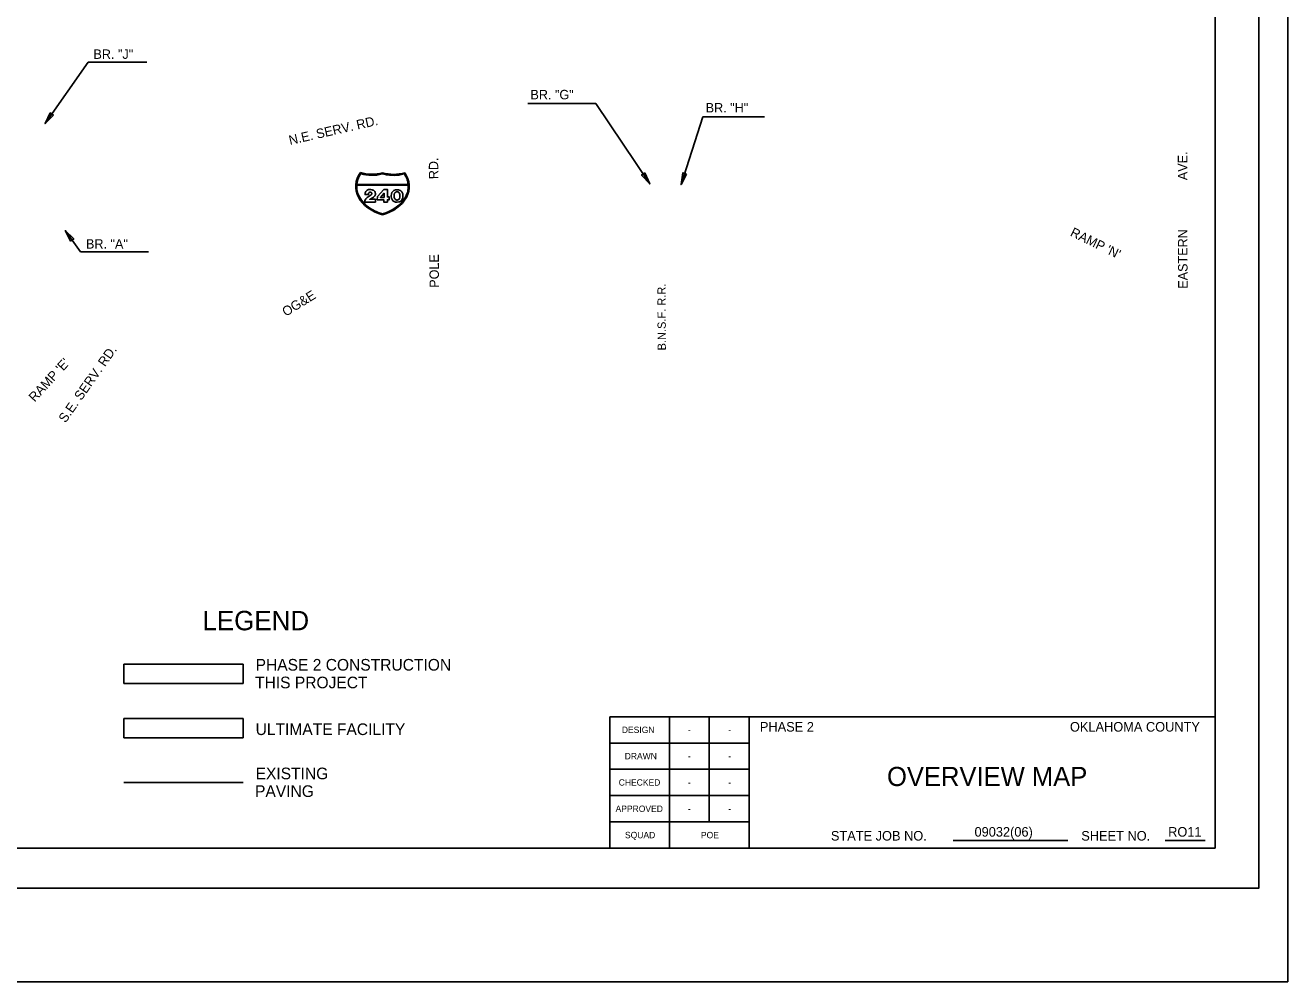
# Model space of a CAD drawing. Extents: x 2140911 to 2156666, y 139570 to 147689.
# Drawn here: x 2151304 to 2156666, y 139570 to 143629 of the extents above; entities that cross this region are included whole.
import ezdxf

# ---------------------------------------------------------------- set-up
doc = ezdxf.new("R2010")
doc.units = 0
for name, color, linetype in [('5', 7, 'Continuous'), ('7', 7, 'Continuous'), ('Default', 7, 'Continuous'), ('NEWCRK', 7, 'Continuous'), ('PR_Shading_Bridge_Phase_4', 7, 'Continuous'), ('PR_Shading_Pavement_Phase_3', 7, 'Continuous'), ('SHT_Plot_Shape_Full', 7, 'Continuous'), ('SHT_Plot_Shape_Half', 7, 'Continuous'), ('SHT_Sheet_Border', 7, 'Continuous'), ('SHT_Standard_Sheet_Lines', 7, 'Continuous'), ('SHT_Standard_Sheet_Txt', 7, 'Continuous'), ('ST-TEXT', 7, 'Continuous'), ('TOPO_Asphalt', 7, 'Continuous')]:
    doc.layers.add(name, color=color, linetype=linetype)

# ---------------------------------------------------------------- blocks, each defined once
blk = doc.blocks.new('ARROWHD')
at = {"layer": 'Default'}
blk.add_lwpolyline([(0.313, -0.054), (0.313, 0.052), (-0.005, -0.001)], close=True, dxfattribs=at)
blk = doc.blocks.new('i-240-shield')
at = {"layer": '7'}
blk.add_line((-18.14, 4.87), (18.76, 4.87), dxfattribs=at)
blk.add_line((-18.14, 4.87), (18.76, 4.87), dxfattribs=at)
for points in [[(-18.19, 4.17), (-18.21, 3.34), (-18.2, 2.74), (-18.15, 2.08), (-18.03, 1.02), (-17.84, 0.03), (-17.61, -0.87), (-17.3, -1.84), (-16.81, -3.04), (-16.3, -4.1), (-15.54, -5.4), (-14.75, -6.55), (-13.83, -7.71), (-12.99, -8.63), (-11.98, -9.62), (-11.44, -10.1), (-10.55, -10.85), (-9.63, -11.55), (-8.66, -12.22), (-7.48, -12.96), (-6.6, -13.47), (-5.36, -14.13), (-3.8, -14.86), (-2.74, -15.3), (-1.39, -15.81), (-0.45, -16.12), (0.31, -16.36), (1.08, -16.12), (2.01, -15.81), (3.36, -15.3), (4.42, -14.86), (5.98, -14.13), (7.23, -13.47), (8.11, -12.96), (9.29, -12.22), (10.26, -11.55), (11.17, -10.85), (12.07, -10.1), (12.61, -9.62), (13.62, -8.63), (14.45, -7.71), (15.37, -6.55), (16.17, -5.4), (16.92, -4.1), (17.44, -3.04), (17.92, -1.84), (18.23, -0.87), (18.46, 0.03), (18.65, 1.02), (18.78, 2.08), (18.82, 2.74), (18.84, 3.34), (18.81, 4.17), (-18.19, 4.17)], [(-12.32, -6.89), (-11.99, -6.14), (-11.64, -5.57), (-11.2, -5.11), (-10.65, -4.57), (-7.85, -2.75), (-7.38, -2.19), (-7.33, -2.12), (-7.33, -1.73), (-7.42, -1.37), (-7.47, -1.29), (-7.71, -1.1), (-8.22, -0.88), (-8.83, -0.88), (-9.35, -1.09), (-9.47, -1.2), (-9.72, -1.6), (-9.72, -2.53), (-12.22, -2.53), (-12.22, -1.73), (-12.11, -1.26), (-12, -0.88), (-11.76, -0.38), (-11.4, 0.02), (-10.73, 0.58), (-10.17, 0.86), (-9.71, 1.06), (-9.12, 1.15), (-8.13, 1.15), (-7.14, 0.97), (-6.57, 0.78), (-6.23, 0.58), (-5.77, 0.29), (-5.42, -0.1), (-5.19, -0.38), (-4.95, -0.78), (-4.84, -1.17), (-4.72, -1.65), (-4.72, -2.45), (-4.96, -2.97), (-5.19, -3.34), (-5.43, -3.64), (-6.08, -4.27), (-6.84, -4.83), (-8.63, -5.78), (-8.79, -5.89), (-4.72, -5.89), (-4.72, -7.91), (-12.49, -7.91), (-12.32, -6.89)], [(1.38, 1.07), (3.92, 1.07), (3.92, -4.15), (5.17, -4.15), (5.17, -6.17), (3.92, -6.17), (3.92, -7.91), (1.2, -7.91), (1.2, -6.17), (-3.37, -6.17), (-3.37, -3.99), (1.38, 1.07)], [(10.93, -7.91), (10.35, -7.91), (9.78, -7.81), (9.22, -7.63), (8.77, -7.44), (7.88, -6.88), (7.52, -6.48), (7.19, -6.01), (6.74, -5), (6.52, -4.06), (6.52, -3.04), (6.74, -2.04), (7.06, -1.04), (7.31, -0.63), (7.65, -0.24), (8.56, 0.5), (9.67, 0.88), (10.79, 1.07), (11.92, 0.88), (13.01, 0.51), (13.5, 0.2), (14.16, -0.53), (14.51, -1.02), (14.85, -1.85), (15.07, -2.86), (15.07, -3.89), (14.85, -4.91), (14.51, -5.82), (14.28, -6.21), (13.94, -6.59), (13.5, -7.06), (13.02, -7.36), (12.57, -7.54), (12.02, -7.72), (10.93, -7.91)], [(1.52, -4.47), (1.52, -1.51), (-1.19, -4.47), (1.52, -4.47)], [(10.17, -6.28), (10.69, -6.37), (10.9, -6.37), (11.42, -6.28), (11.94, -6.02), (12.36, -5.69), (12.57, -5.34), (12.77, -4.38), (12.88, -3.51), (12.77, -2.38), (12.57, -1.6), (12.36, -1.25), (12.15, -0.99), (12.04, -0.91), (11.73, -0.73), (11.31, -0.56), (11, -0.47), (10.69, -0.47), (10.17, -0.56), (9.96, -0.64), (9.65, -0.82), (9.23, -1.17), (9.02, -1.51), (8.81, -2.56), (8.71, -3.51), (8.81, -4.56), (9.13, -5.51), (9.44, -5.85), (9.65, -6.02), (10.17, -6.28)]]:
    blk.add_lwpolyline(points, dxfattribs=at)
for points in [[(-18.19, 4.17), (-18.21, 3.34), (-18.2, 2.74), (-18.15, 2.08), (-18.03, 1.02), (-17.84, 0.03), (-17.61, -0.87), (-17.3, -1.84), (-16.81, -3.04), (-16.3, -4.1), (-15.54, -5.4), (-14.75, -6.55), (-13.83, -7.71), (-12.99, -8.63), (-11.98, -9.62), (-11.44, -10.1), (-10.55, -10.85), (-9.63, -11.55), (-8.66, -12.22), (-7.48, -12.96), (-6.6, -13.47), (-5.36, -14.13), (-3.8, -14.86), (-2.74, -15.3), (-1.39, -15.81), (-0.45, -16.12), (0.31, -16.36), (1.08, -16.12), (2.01, -15.81), (3.36, -15.3), (4.42, -14.86), (5.98, -14.13), (7.23, -13.47), (8.11, -12.96), (9.29, -12.22), (10.26, -11.55), (11.17, -10.85), (12.07, -10.1), (12.61, -9.62), (13.62, -8.63), (14.45, -7.71), (15.37, -6.55), (16.17, -5.4), (16.92, -4.1), (17.44, -3.04), (17.92, -1.84), (18.23, -0.87), (18.46, 0.03), (18.65, 1.02), (18.78, 2.08), (18.82, 2.74), (18.84, 3.34), (18.81, 4.17)], [(-12.32, -6.89), (-11.99, -6.14), (-11.64, -5.57), (-11.2, -5.11), (-10.65, -4.57), (-7.85, -2.75), (-7.38, -2.19), (-7.33, -2.12), (-7.33, -1.73), (-7.42, -1.37), (-7.47, -1.29), (-7.71, -1.1), (-8.22, -0.88), (-8.83, -0.88), (-9.35, -1.09), (-9.47, -1.2), (-9.72, -1.6), (-9.72, -2.53), (-12.22, -2.53), (-12.22, -1.73), (-12.11, -1.26), (-12, -0.88), (-11.76, -0.38), (-11.4, 0.02), (-10.73, 0.58), (-10.17, 0.86), (-9.71, 1.06), (-9.12, 1.15), (-8.13, 1.15), (-7.14, 0.97), (-6.57, 0.78), (-6.23, 0.58), (-5.77, 0.29), (-5.42, -0.1), (-5.19, -0.38), (-4.95, -0.78), (-4.84, -1.17), (-4.72, -1.65), (-4.72, -2.45), (-4.96, -2.97), (-5.19, -3.34), (-5.43, -3.64), (-6.08, -4.27), (-6.84, -4.83), (-8.63, -5.78), (-8.79, -5.89), (-4.72, -5.89), (-4.72, -7.91), (-12.49, -7.91)], [(1.38, 1.07), (3.92, 1.07), (3.92, -4.15), (5.17, -4.15), (5.17, -6.17), (3.92, -6.17), (3.92, -7.91), (1.2, -7.91), (1.2, -6.17), (-3.37, -6.17), (-3.37, -3.99)], [(10.93, -7.91), (10.35, -7.91), (9.78, -7.81), (9.22, -7.63), (8.77, -7.44), (7.88, -6.88), (7.52, -6.48), (7.19, -6.01), (6.74, -5), (6.52, -4.06), (6.52, -3.04), (6.74, -2.04), (7.06, -1.04), (7.31, -0.63), (7.65, -0.24), (8.56, 0.5), (9.67, 0.88), (10.79, 1.07), (11.92, 0.88), (13.01, 0.51), (13.5, 0.2), (14.16, -0.53), (14.51, -1.02), (14.85, -1.85), (15.07, -2.86), (15.07, -3.89), (14.85, -4.91), (14.51, -5.82), (14.28, -6.21), (13.94, -6.59), (13.5, -7.06), (13.02, -7.36), (12.57, -7.54), (12.02, -7.72)], [(1.52, -1.51), (1.52, -4.47), (-1.19, -4.47)], [(9.44, -5.85), (9.13, -5.51), (9.13, -5.51), (8.81, -4.56), (8.71, -3.51), (8.81, -2.56), (9.02, -1.51), (9.23, -1.17), (9.65, -0.82), (9.96, -0.64), (10.17, -0.56), (10.69, -0.47), (11, -0.47), (11.31, -0.56), (11.73, -0.73), (12.04, -0.91), (12.15, -0.99), (12.36, -1.25), (12.57, -1.6), (12.77, -2.38), (12.88, -3.51), (12.77, -4.38), (12.57, -5.34), (12.36, -5.69), (11.94, -6.02), (11.42, -6.28), (10.9, -6.37), (10.69, -6.37), (10.17, -6.28), (9.65, -6.02)]]:
    blk.add_lwpolyline(points, close=True, dxfattribs=at)
for centre, major_axis, start_param, end_param in [((12.1, 3.38), (31.01, 0), 2.678593, 4.322471), ((-7.55, 27.2), (-21.16, 0), 1.177968, 1.951302), ((-11.47, 3.38), (-31.01, 0), 1.960714, 3.604592), ((8.17, 27.2), (21.16, 0), 4.331883, 5.105218)]:
    blk.add_ellipse(centre, major_axis=major_axis, ratio=0.713476, start_param=start_param, end_param=end_param, dxfattribs=at)
for points in [[(-15.35, 12.45), (-16.31, 11), (-17.04, 9.48), (-17.83, 6.92), (-18.03, 5.9), (-18.14, 4.87)], [(-15.35, 12.45), (-16.31, 11), (-17.04, 9.48), (-17.83, 6.92), (-18.03, 5.9), (-18.14, 4.87)], [(-15.35, 12.45), (-13.8, 12.02), (-12.19, 11.72), (-6.9, 11.19), (-3.13, 11.51), (0.31, 12.46)], [(0.31, 12.46), (-3.13, 11.51), (-6.9, 11.19), (-12.19, 11.72), (-13.8, 12.02), (-15.35, 12.45)], [(0.31, 12.46), (1.96, 12.01), (3.68, 11.69), (8.98, 11.21), (12.63, 11.53), (15.98, 12.45)], [(15.98, 12.45), (12.63, 11.53), (8.98, 11.21), (3.68, 11.69), (1.96, 12.01), (0.31, 12.46)], [(18.76, 4.87), (18.67, 5.78), (18.5, 6.68), (17.77, 9.25), (17.01, 10.89), (15.98, 12.45)], [(18.76, 4.87), (18.67, 5.78), (18.5, 6.68), (17.77, 9.25), (17.01, 10.89), (15.98, 12.45)]]:
    blk.add_open_spline(points, degree=3, dxfattribs=at)
at = {"layer": 'Default'}
for p, q in [((-12.12, -7.59), (-12.12, -7.59)), ((1.52, -4.47), (1.52, -4.47)), ((1.52, -7.59), (1.52, -7.59))]:
    blk.add_line(p, q, dxfattribs=at)

msp = doc.modelspace()

# ---------------------------------------------------------------- linework, layer by layer
at = {"layer": '5'}
for p, q in [((2151388.7, 143212.6), (2151570.8, 143473.2)), ((2151821.1, 143473.2), (2151570.8, 143473.2)), ((2153438.3, 143297), (2153726.9, 143297)), ((2153956.2, 142956.9), (2153726.9, 143297)), ((2154089.8, 142953.8), (2154182.7, 143241.1)), ((2154182.7, 143241.1), (2154443.5, 143241.1)), ((2151474.5, 142757.6), (2151539.1, 142667.8)), ((2151827.5, 142667.8), (2151539.1, 142667.8))]:
    msp.add_line(p, q, dxfattribs=at)
at = {"layer": '7'}
msp.add_lwpolyline([(2152712.3, 142950.5), (2152712.6, 142954.6), (2152930.5, 142953.7), (2152930.8, 142949.6)], close=True, dxfattribs=at)
at = {"layer": 'NEWCRK'}
for p, q in [((2151722.6, 140917), (2152230.2, 140917)), ((2151722.6, 140835.6), (2152230.2, 140835.6)), ((2151722.6, 140686.4), (2152230.2, 140686.4)), ((2151722.6, 140604.9), (2152230.2, 140604.9))]:
    msp.add_line(p, q, dxfattribs=at)
at = {"layer": 'PR_Shading_Bridge_Phase_4'}
for p, q in [((2151722.6, 140917), (2151722.6, 140835.6)), ((2152230.2, 140917), (2151722.6, 140917)), ((2152230.2, 140835.6), (2152230.2, 140917)), ((2151722.6, 140835.6), (2152230.2, 140835.6))]:
    msp.add_line(p, q, dxfattribs=at)
at = {"layer": 'PR_Shading_Pavement_Phase_3'}
for p, q in [((2151722.6, 140686.4), (2151722.6, 140604.9)), ((2152230.2, 140686.4), (2151722.6, 140686.4)), ((2152230.2, 140604.9), (2152230.2, 140686.4)), ((2151722.6, 140604.9), (2152230.2, 140604.9))]:
    msp.add_line(p, q, dxfattribs=at)
at = {"layer": 'SHT_Plot_Shape_Full'}
msp.add_lwpolyline([(2144487.6, 147688.9), (2156666.2, 147688.9), (2156666.2, 139569.8), (2144487.6, 139569.8)], close=True, dxfattribs=at)
at = {"layer": 'SHT_Plot_Shape_Half'}
msp.add_lwpolyline([(2145041.5, 147409.9), (2156543.6, 147409.9), (2156543.6, 139967.3), (2145041.5, 139967.3)], close=True, dxfattribs=at)
at = {"layer": 'SHT_Sheet_Border'}
for p, q in [((2153786.5, 140136.5), (2153786.5, 140694.7)), ((2153786.5, 140694.7), (2156357.5, 140694.7)), ((2154378.5, 140136.5), (2154378.5, 140694.9))]:
    msp.add_line(p, q, dxfattribs=at)
msp.add_lwpolyline([(2156357.5, 140136.5), (2145701.2, 140136.5), (2145701.2, 147240.7), (2156357.5, 147240.7)], close=True, dxfattribs=at)
at = {"layer": 'SHT_Standard_Sheet_Lines'}
for p, q in [((2154040.2, 140136.5), (2154040.2, 140694.9)), ((2154209.3, 140248.2), (2154209.3, 140694.9)), ((2155244.8, 140169), (2155732, 140169)), ((2156146.3, 140169), (2156316.2, 140169))]:
    msp.add_line(p, q, dxfattribs=at)
for points in [[(2154378.5, 140583), (2153786.5, 140583)], [(2154378.5, 140471.4), (2153786.5, 140471.4)], [(2154378.5, 140359.7), (2153786.5, 140359.7)], [(2154378.5, 140248.1), (2153786.5, 140248.1)]]:
    msp.add_lwpolyline(points, dxfattribs=at)
at = {"layer": 'TOPO_Asphalt'}
msp.add_line((2151722.6, 140415), (2152230.2, 140415), dxfattribs=at)

# ---------------------------------------------------------------- block references
at = {"layer": '5'}
for p, xscale, yscale, rotation in [((2151388.7, 143212.6), 157.48000000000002, 157.48, 55.04814174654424), ((2153956.2, 142956.9), 157.48, 157.48000000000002, 123.98858803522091), ((2154089.8, 142953.8), 157.48000000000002, 157.48000000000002, 72.09080996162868), ((2151474.5, 142757.6), 157.48, 157.48000000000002, -54.22993189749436)]:
    msp.add_blockref('ARROWHD', p, dxfattribs=dict(at, xscale=xscale, yscale=yscale, rotation=rotation))
at = {"layer": '7', "xscale": 5.905500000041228, "yscale": 5.905500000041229, "rotation": -0.2304623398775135}
msp.add_blockref('i-240-shield', (2152819.6, 142925.4), dxfattribs=at)

# ---------------------------------------------------------------- texts
at = {"layer": 'SHT_Standard_Sheet_Txt'}
for s, height, p in [('DESIGN', 27.06, (2153838, 140625.4)), ('OKLAHOMA COUNTY', 40.596, (2155741.2, 140631.5)), ('-', 27.1, (2154118.2, 140625.4)), ('-', 27.1, (2154290.2, 140625.4)), ('DRAWN', 27.06, (2153850.1, 140513.8)), ('-', 27.1, (2154118.2, 140513.8)), ('-', 27.1, (2154290.2, 140513.8)), ('OVERVIEW MAP', 81.191, (2154964.3, 140400.5)), ('CHECKED', 27.06, (2153824.7, 140402.2)), ('-', 27.1, (2154118.2, 140402.1)), ('-', 27.1, (2154290.2, 140402.1)), ('APPROVED', 27.06, (2153811.4, 140290.5)), ('-', 27.1, (2154118.2, 140290.4)), ('-', 27.1, (2154290.2, 140290.4)), ('09032(06)', 40.6, (2155335.9, 140185.7)), ('RO11', 40.6, (2156158.3, 140185.7)), ('SQUAD', 27.06, (2153851.3, 140178.9)), ('POE', 27.06, (2154173.9, 140178.8)), ('STATE JOB NO.', 40.596, (2154726, 140169)), ('SHEET NO. ', 40.6, (2155789.4, 140169))]:
    msp.add_text(s, height=height, dxfattribs=at).set_placement(p)
msp.add_text('PHASE 2', height=40.6, rotation=0, dxfattribs=at).set_placement((2154424.4, 140631.5))
at = {"layer": 'ST-TEXT'}
for s, height, rotation, p in [('BR. "J"', 40, 360, (2151593.9, 143486.8)), ('BR. "G"', 40, 360, (2153449.9, 143315.1)), ('N.E. SERV. RD.', 40, 12.8297, (2152428.7, 143121.2)), ('RD.', 40, 90.1579, (2153058.4, 142976.1)), ('EASTERN              AVE.', 40, 90.1579, (2156240.8, 142511.2)), ("RAMP 'N'", 40, 333.9781, (2155739.1, 142737.2)), ('POLE', 40, 90.1579, (2153061.2, 142515.3)), ('B.N.S.F. R.R.', 35, 90.1579, (2154024.9, 142249.4)), ('OG&E', 40, 31.6564, (2152410.9, 142391.9)), ('S.E. SERV. RD.', 40, 54.9105, (2151475.2, 141939.2)), ("RAMP 'E'", 40, 47.4663, (2151344.2, 142027.8)), ('LEGEND', 82.42, 360, (2152056.6, 141061.5)), ('PHASE 2 CONSTRUCTION', 49.455, 360, (2152282.6, 140890.3)), ('THIS PROJECT', 49.455, 360, (2152280.2, 140815.2)), ('ULTIMATE FACILITY', 49.455, 360, (2152282.6, 140616.8)), ('EXISTING', 49.45, 360, (2152282.6, 140429.1)), ('PAVING', 49.45, 360, (2152280.2, 140354))]:
    msp.add_text(s, height=height, rotation=rotation, dxfattribs=at).set_placement(p)
for s, p in [('BR. "H"', (2154194.2, 143259.2)), ('BR. "A"', (2151562.2, 142681.5))]:
    msp.add_text(s, height=40, dxfattribs=at).set_placement(p)

doc.saveas('drawing.dxf')
